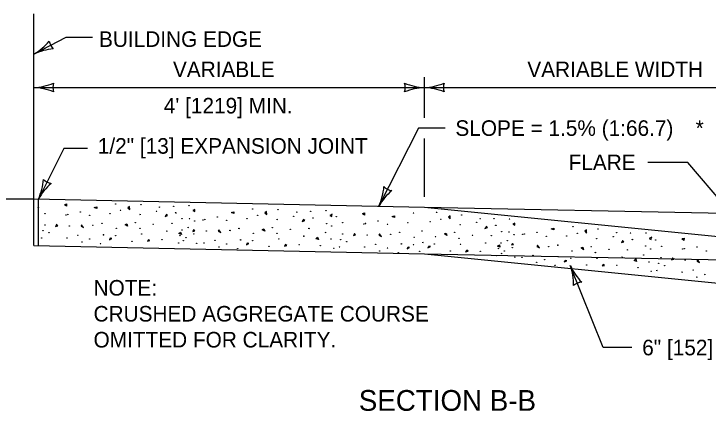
# Model space of a CAD drawing. Extents: x 49987.9 to 50021, y 49987.6 to 50011.4.
# Drawn here: x 50004.279 to 50006.956, y 50003.256 to 50004.787 of the extents above; entities that cross this region are included whole.
import ezdxf

# ---------------------------------------------------------------- set-up
doc = ezdxf.new("R2010")
doc.units = 0
for name, color, linetype in [('Level 1', 7, 'Continuous'), ('Level 2', 7, 'Continuous'), ('Level 3', 7, 'Continuous'), ('Level 4', 7, 'Continuous')]:
    doc.layers.add(name, color=color, linetype=linetype)

msp = doc.modelspace()

# ---------------------------------------------------------------- linework, layer by layer
at = {"layer": 'Level 1'}
for p, q in [((50004.3555, 50004.0737), (50004.3555, 50004.7866)), ((50003.4796, 50004.0736), (50004.3555, 50004.0737)), ((50004.3555, 50003.8937), (50004.3555, 50004.0737)), ((50004.3555, 50004.0737), (50005.8615, 50004.0421)), ((50004.3733, 50003.8933), (50004.3733, 50004.0733)), ((50004.5887, 50004.0402), (50004.5982, 50004.0433)), ((50004.5887, 50004.0402), (50004.5982, 50004.0433)), ((50004.5982, 50004.0371), (50004.5887, 50004.0402)), ((50004.5982, 50004.0371), (50004.5887, 50004.0402)), ((50004.5982, 50004.0433), (50004.5982, 50004.0371)), ((50004.5982, 50004.0433), (50004.5982, 50004.0371)), ((50004.9759, 50004.0334), (50004.9681, 50004.0288)), ((50004.9681, 50004.0288), (50004.9759, 50004.0249)), ((50004.9681, 50004.0288), (50004.9759, 50004.0249)), ((50004.9759, 50004.0249), (50004.9759, 50004.0334)), ((50004.9759, 50004.0249), (50004.9759, 50004.0326)), ((50005.1173, 50004.0209), (50005.1268, 50004.024)), ((50005.1173, 50004.0209), (50005.1268, 50004.024)), ((50005.1268, 50004.024), (50005.1268, 50004.0178)), ((50005.1268, 50004.024), (50005.1268, 50004.0178)), ((50005.8615, 50004.0421), (50007.3675, 50003.8919)), ((50005.8615, 50004.0421), (50007.3675, 50004.0119)), ((50005.1268, 50004.0178), (50005.1173, 50004.0209)), ((50005.1268, 50004.0178), (50005.1173, 50004.0209)), ((50005.7372, 50004.0055), (50005.7467, 50004.0086)), ((50005.7372, 50004.0055), (50005.7467, 50004.0086)), ((50005.7467, 50004.0024), (50005.7372, 50004.0055)), ((50005.7467, 50004.0024), (50005.7372, 50004.0055)), ((50005.7467, 50004.0086), (50005.7467, 50004.0024)), ((50005.7467, 50004.0086), (50005.7467, 50004.0024)), ((50004.7081, 50003.9744), (50004.7143, 50003.9774)), ((50004.7081, 50003.9744), (50004.7143, 50003.9774)), ((50004.7174, 50003.9681), (50004.7081, 50003.9744)), ((50004.7174, 50003.9681), (50004.7081, 50003.9744)), ((50004.7143, 50003.9774), (50004.7174, 50003.9681)), ((50004.7143, 50003.9774), (50004.7174, 50003.9681)), ((50006.211, 50003.9803), (50006.2029, 50003.9763)), ((50006.2029, 50003.9763), (50006.2104, 50003.9719)), ((50006.2029, 50003.9763), (50006.2104, 50003.9719)), ((50006.2104, 50003.9719), (50006.211, 50003.9803)), ((50006.2104, 50003.9719), (50006.2109, 50003.9796)), ((50004.915, 50003.9398), (50004.9214, 50003.946)), ((50004.915, 50003.9398), (50004.9214, 50003.946)), ((50004.9214, 50003.946), (50004.9245, 50003.9366)), ((50004.9214, 50003.946), (50004.9245, 50003.9366)), ((50004.9719, 50003.9546), (50004.9682, 50003.9486)), ((50004.9682, 50003.9486), (50004.9763, 50003.9506)), ((50004.9763, 50003.9506), (50004.9719, 50003.9546)), ((50005.2367, 50003.9551), (50005.2429, 50003.9581)), ((50005.2367, 50003.9551), (50005.2429, 50003.9581)), ((50005.246, 50003.9488), (50005.2367, 50003.9551)), ((50005.246, 50003.9488), (50005.2367, 50003.9551)), ((50005.2429, 50003.9581), (50005.246, 50003.9488)), ((50005.2429, 50003.9581), (50005.246, 50003.9488)), ((50006.3512, 50003.9584), (50006.3609, 50003.9609)), ((50006.3512, 50003.9584), (50006.3609, 50003.9609)), ((50006.3605, 50003.9547), (50006.3512, 50003.9584)), ((50006.3605, 50003.9547), (50006.3512, 50003.9584)), ((50006.3609, 50003.9609), (50006.3605, 50003.9547)), ((50006.3609, 50003.9609), (50006.3605, 50003.9547)), ((50004.7972, 50003.9165), (50004.7934, 50003.9109)), ((50004.8025, 50003.913), (50004.7972, 50003.9165)), ((50004.9245, 50003.9366), (50004.915, 50003.9398)), ((50004.9245, 50003.9366), (50004.915, 50003.9398)), ((50005.4436, 50003.9205), (50005.45, 50003.9267)), ((50005.4436, 50003.9205), (50005.45, 50003.9267)), ((50005.4531, 50003.9173), (50005.4436, 50003.9205)), ((50005.4531, 50003.9173), (50005.4436, 50003.9205)), ((50005.45, 50003.9267), (50005.4531, 50003.9173)), ((50005.45, 50003.9267), (50005.4531, 50003.9173)), ((50005.9398, 50003.9394), (50005.9462, 50003.942)), ((50005.9398, 50003.9394), (50005.9462, 50003.942)), ((50005.9487, 50003.9325), (50005.9398, 50003.9394)), ((50005.9487, 50003.9325), (50005.9398, 50003.9394)), ((50005.9462, 50003.942), (50005.9487, 50003.9325)), ((50005.9462, 50003.942), (50005.9487, 50003.9325)), ((50004.3555, 50003.8937), (50005.8615, 50003.8621)), ((50004.7934, 50003.9109), (50004.8025, 50003.913)), ((50006.144, 50003.891), (50006.1508, 50003.8968)), ((50006.144, 50003.891), (50006.1508, 50003.8968)), ((50006.1532, 50003.8872), (50006.144, 50003.891)), ((50006.1532, 50003.8872), (50006.144, 50003.891)), ((50006.1508, 50003.8968), (50006.1532, 50003.8872)), ((50006.1508, 50003.8968), (50006.1532, 50003.8872)), ((50006.2017, 50003.9021), (50006.1976, 50003.8963)), ((50006.1976, 50003.8963), (50006.2058, 50003.8977)), ((50006.2058, 50003.8977), (50006.2017, 50003.9021)), ((50005.8615, 50003.8621), (50007.3675, 50003.7119)), ((50006.0248, 50003.8757), (50006.0207, 50003.8703)), ((50006.0207, 50003.8703), (50006.0299, 50003.8718)), ((50006.0299, 50003.8718), (50006.0248, 50003.8757)), ((50006.466, 50003.8848), (50006.4723, 50003.8874)), ((50006.466, 50003.8848), (50006.4723, 50003.8874)), ((50006.4748, 50003.8779), (50006.466, 50003.8848)), ((50006.4748, 50003.8779), (50006.466, 50003.8848)), ((50006.4723, 50003.8874), (50006.4748, 50003.8779)), ((50006.4723, 50003.8874), (50006.4748, 50003.8779)), ((50006.6701, 50003.8365), (50006.6769, 50003.8422)), ((50006.6701, 50003.8365), (50006.6769, 50003.8422)), ((50006.6794, 50003.8326), (50006.6701, 50003.8365)), ((50006.6794, 50003.8326), (50006.6701, 50003.8365)), ((50006.6769, 50003.8422), (50006.6794, 50003.8326)), ((50006.6769, 50003.8422), (50006.6794, 50003.8326))]:
    msp.add_line(p, q, dxfattribs=at)
for points in [[(50004.4747, 50004.0524), (50004.4817, 50004.0542), (50004.4817, 50004.0454), (50004.474, 50004.0511)], [(50004.4747, 50004.0524), (50004.4817, 50004.0542), (50004.4817, 50004.0454), (50004.474, 50004.0511)], [(50004.7243, 50004.0448), (50004.718, 50004.0397), (50004.7255, 50004.0326), (50004.7243, 50004.0448)], [(50004.7243, 50004.0448), (50004.718, 50004.0397), (50004.7255, 50004.0326), (50004.7243, 50004.0448)], [(50005.2529, 50004.0255), (50005.2466, 50004.0204), (50005.2541, 50004.0133), (50005.2529, 50004.0255)], [(50005.2529, 50004.0255), (50005.2466, 50004.0204), (50005.2541, 50004.0133), (50005.2529, 50004.0255)], [(50004.8671, 50004.0133), (50004.8619, 50004.0057), (50004.8715, 50004.0095), (50004.8658, 50004.0141)], [(50004.8671, 50004.0133), (50004.8619, 50004.0057), (50004.8715, 50004.0095), (50004.8658, 50004.0141)], [(50005.5064, 50004.0152), (50005.4967, 50004.0095), (50005.5045, 50004.0056), (50005.5045, 50004.0133)], [(50005.5064, 50004.0152), (50005.4967, 50004.0095), (50005.5045, 50004.0056), (50005.5045, 50004.0133)], [(50005.6232, 50004.0177), (50005.6302, 50004.0195), (50005.6302, 50004.0107), (50005.6225, 50004.0164)], [(50005.6232, 50004.0177), (50005.6302, 50004.0195), (50005.6302, 50004.0107), (50005.6225, 50004.0164)], [(50005.9607, 50004.0085), (50005.9541, 50004.0039), (50005.9611, 50003.9963), (50005.9607, 50004.0085)], [(50005.9607, 50004.0085), (50005.9541, 50004.0039), (50005.9611, 50003.9963), (50005.9607, 50004.0085)], [(50004.4439, 50003.975), (50004.4396, 50003.9679), (50004.4477, 50003.9699), (50004.4421, 50003.975)], [(50004.4439, 50003.975), (50004.4396, 50003.9679), (50004.4477, 50003.9699), (50004.4421, 50003.975)], [(50004.54, 50003.9744), (50004.5375, 50003.9686), (50004.5477, 50003.9641), (50004.54, 50003.9744)], [(50004.54, 50003.9744), (50004.5375, 50003.9686), (50004.5477, 50003.9641), (50004.54, 50003.9744)], [(50005.3957, 50003.994), (50005.3905, 50003.9864), (50005.4001, 50003.9902), (50005.3944, 50003.9948)], [(50005.3957, 50003.994), (50005.3905, 50003.9864), (50005.4001, 50003.9902), (50005.3944, 50003.9948)], [(50005.0686, 50003.9551), (50005.0661, 50003.9493), (50005.0763, 50003.9448), (50005.0686, 50003.9551)], [(50005.0686, 50003.9551), (50005.0661, 50003.9493), (50005.0763, 50003.9448), (50005.0686, 50003.9551)], [(50006.1011, 50003.9676), (50006.0954, 50003.9603), (50006.1052, 50003.9635), (50006.0998, 50003.9685)], [(50006.1011, 50003.9676), (50006.0954, 50003.9603), (50006.1052, 50003.9635), (50006.0998, 50003.9685)], [(50006.4868, 50003.954), (50006.4802, 50003.9493), (50006.4872, 50003.9417), (50006.4868, 50003.954)], [(50006.4868, 50003.954), (50006.4802, 50003.9493), (50006.4872, 50003.9417), (50006.4868, 50003.954)], [(50004.6495, 50003.9219), (50004.6468, 50003.9161), (50004.6564, 50003.9212), (50004.6501, 50003.9225)], [(50004.6495, 50003.9219), (50004.6468, 50003.9161), (50004.6564, 50003.9212), (50004.6501, 50003.9225)], [(50005.5924, 50003.9403), (50005.5881, 50003.9332), (50005.5962, 50003.9352), (50005.5906, 50003.9403)], [(50005.5924, 50003.9403), (50005.5881, 50003.9332), (50005.5962, 50003.9352), (50005.5906, 50003.9403)], [(50005.6885, 50003.9397), (50005.686, 50003.9339), (50005.6962, 50003.9294), (50005.6885, 50003.9397)], [(50005.6885, 50003.9397), (50005.686, 50003.9339), (50005.6962, 50003.9294), (50005.6885, 50003.9397)], [(50006.7391, 50003.9268), (50006.729, 50003.9217), (50006.7365, 50003.9173), (50006.7371, 50003.925)], [(50006.7391, 50003.9268), (50006.729, 50003.9217), (50006.7365, 50003.9173), (50006.7371, 50003.925)], [(50006.8558, 50003.9214), (50006.8629, 50003.9228), (50006.8623, 50003.914), (50006.855, 50003.9202)], [(50006.8558, 50003.9214), (50006.8629, 50003.9228), (50006.8623, 50003.914), (50006.855, 50003.9202)], [(50005.1781, 50003.9026), (50005.1754, 50003.8968), (50005.185, 50003.9019), (50005.1787, 50003.9032)], [(50005.1781, 50003.9026), (50005.1754, 50003.8968), (50005.185, 50003.9019), (50005.1787, 50003.9032)], [(50005.3259, 50003.8975), (50005.322, 50003.8916), (50005.3311, 50003.8937), (50005.3253, 50003.8975)], [(50005.3259, 50003.8975), (50005.322, 50003.8916), (50005.3311, 50003.8937), (50005.3253, 50003.8975)], [(50005.8779, 50003.8909), (50005.8748, 50003.8853), (50005.8847, 50003.8898), (50005.8785, 50003.8915)], [(50005.8779, 50003.8909), (50005.8748, 50003.8853), (50005.8847, 50003.8898), (50005.8785, 50003.8915)], [(50006.2982, 50003.896), (50006.2954, 50003.8904), (50006.3052, 50003.8853), (50006.2982, 50003.896)], [(50006.2982, 50003.896), (50006.2954, 50003.8904), (50006.3052, 50003.8853), (50006.2982, 50003.896)], [(50006.6272, 50003.913), (50006.6215, 50003.9058), (50006.6313, 50003.9089), (50006.626, 50003.9139)], [(50006.6272, 50003.913), (50006.6215, 50003.9058), (50006.6313, 50003.9089), (50006.626, 50003.9139)], [(50005.798, 50003.8872), (50005.7953, 50003.8814), (50005.8049, 50003.8865), (50005.7986, 50003.8878)], [(50005.798, 50003.8872), (50005.7953, 50003.8814), (50005.8049, 50003.8865), (50005.7986, 50003.8878)], [(50006.404, 50003.8363), (50006.4009, 50003.8307), (50006.4108, 50003.8352), (50006.4046, 50003.8369)], [(50006.404, 50003.8363), (50006.4009, 50003.8307), (50006.4108, 50003.8352), (50006.4046, 50003.8369)], [(50006.8199, 50003.8463), (50006.8151, 50003.8395), (50006.8233, 50003.8409), (50006.8181, 50003.8464)], [(50006.8199, 50003.8463), (50006.8151, 50003.8395), (50006.8233, 50003.8409), (50006.8181, 50003.8464)], [(50006.9157, 50003.8393), (50006.9128, 50003.8336), (50006.9227, 50003.8285), (50006.9157, 50003.8393)], [(50006.9157, 50003.8393), (50006.9128, 50003.8336), (50006.9227, 50003.8285), (50006.9157, 50003.8393)], [(50006.5511, 50003.8214), (50006.5468, 50003.8158), (50006.556, 50003.8172), (50006.5505, 50003.8214)], [(50006.5511, 50003.8214), (50006.5468, 50003.8158), (50006.556, 50003.8172), (50006.5505, 50003.8214)]]:
    msp.add_lwpolyline(points, dxfattribs=at)
for centre in [(50004.6713, 50004.0544), (50004.6713, 50004.0544), (50004.7686, 50004.0513), (50004.7686, 50004.0513), (50004.3733, 50004.0397), (50004.3733, 50004.0397), (50004.5345, 50004.0231), (50004.5345, 50004.0231), (50004.6897, 50004.0293), (50004.6897, 50004.0293), (50004.8287, 50004.0261), (50004.8287, 50004.0261), (50004.8408, 50004.0419), (50004.8408, 50004.0419), (50004.8945, 50004.0449), (50004.8945, 50004.0449), (50004.954, 50004.0481), (50004.954, 50004.0481), (50005.1999, 50004.0351), (50005.1999, 50004.0351), (50005.2972, 50004.032), (50005.2972, 50004.032), (50005.3694, 50004.0226), (50005.3694, 50004.0226), (50005.4231, 50004.0256), (50005.4231, 50004.0256), (50005.4826, 50004.0288), (50005.4826, 50004.0288), (50005.9085, 50004.0217), (50005.9085, 50004.0217), (50004.3983, 50004.0168), (50004.3983, 50004.0168), (50004.4797, 50004.0121), (50004.4797, 50004.0121), (50004.4862, 50004.0136), (50004.4862, 50004.0136), (50004.5709, 50004.0105), (50004.5709, 50004.0105), (50004.6494, 50004.0168), (50004.6494, 50004.0168), (50004.7655, 50004.0136), (50004.7655, 50004.0136), (50004.9019, 50004.0204), (50004.9019, 50004.0204), (50004.9036, 50004.0199), (50004.9036, 50004.0199), (50004.9269, 50003.9975), (50004.9269, 50003.9975), (50004.9558, 50003.998), (50004.9558, 50003.998), (50005.0631, 50004.0038), (50005.0631, 50004.0038), (50005.178, 50003.9975), (50005.178, 50003.9975), (50005.2183, 50004.01), (50005.2183, 50004.01), (50005.3573, 50004.0068), (50005.3573, 50004.0068), (50005.4322, 50004.0006), (50005.4322, 50004.0006), (50005.5218, 50004.005), (50005.5218, 50004.005), (50005.8198, 50004.0197), (50005.8198, 50004.0197), (50005.9251, 50003.9954), (50005.9251, 50003.9954), (50006.0053, 50004.0121), (50006.0053, 50004.0121), (50006.0767, 50003.9978), (50006.0767, 50003.9978), (50006.1305, 50003.9973), (50006.1305, 50003.9973), (50006.19, 50003.9965), (50006.19, 50003.9965), (50004.3983, 50003.9728), (50004.3983, 50003.9728), (50004.4925, 50003.9697), (50004.4925, 50003.9697), (50004.583, 50003.9714), (50004.583, 50003.9714), (50004.618, 50003.9791), (50004.618, 50003.9791), (50004.7467, 50003.9822), (50004.7467, 50003.9822), (50004.8157, 50003.976), (50004.8157, 50003.976), (50004.8879, 50003.9791), (50004.8879, 50003.9791), (50004.9757, 50003.9885), (50004.9757, 50003.9885), (50005.0083, 50003.9928), (50005.0083, 50003.9928), (50005.0148, 50003.9943), (50005.0148, 50003.9943), (50005.0995, 50003.9912), (50005.0995, 50003.9912), (50005.2941, 50003.9943), (50005.2941, 50003.9943), (50005.4844, 50003.9787), (50005.4844, 50003.9787), (50005.5043, 50003.9692), (50005.5043, 50003.9692), (50005.5468, 50003.9821), (50005.5468, 50003.9821), (50005.6282, 50003.9774), (50005.6282, 50003.9774), (50005.6347, 50003.9789), (50005.6347, 50003.9789), (50005.683, 50003.9884), (50005.683, 50003.9884), (50005.7194, 50003.9758), (50005.7194, 50003.9758), (50005.7979, 50003.9821), (50005.7979, 50003.9821), (50005.884, 50003.9856), (50005.884, 50003.9856), (50005.9997, 50003.9747), (50005.9997, 50003.9747), (50006.0636, 50003.983), (50006.0636, 50003.983), (50006.1362, 50003.9724), (50006.1362, 50003.9724), (50006.1379, 50003.9717), (50006.1379, 50003.9717), (50004.3907, 50003.951), (50004.3907, 50003.951), (50004.414, 50003.9432), (50004.414, 50003.9432), (50004.6738, 50003.9604), (50004.6738, 50003.9604), (50004.7646, 50003.9604), (50004.7646, 50003.9604), (50004.8681, 50003.9495), (50004.8681, 50003.9495), (50004.9269, 50003.9535), (50004.9511, 50003.9635), (50004.9511, 50003.9635), (50005.0211, 50003.9504), (50005.0211, 50003.9504), (50005.1116, 50003.9521), (50005.1116, 50003.9521), (50005.1466, 50003.9598), (50005.1466, 50003.9598), (50005.2753, 50003.9629), (50005.2753, 50003.9629), (50005.3443, 50003.9567), (50005.3443, 50003.9567), (50005.4165, 50003.9598), (50005.4165, 50003.9598), (50005.4797, 50003.9442), (50005.4797, 50003.9442), (50005.7665, 50003.9444), (50005.7665, 50003.9444), (50005.852, 50003.9499), (50005.852, 50003.9499), (50005.9788, 50003.9446), (50005.9788, 50003.9446), (50006.1597, 50003.9478), (50006.1597, 50003.9478), (50006.1885, 50003.9464), (50006.1885, 50003.9464), (50006.2959, 50003.945), (50006.2959, 50003.945), (50006.4346, 50003.9671), (50006.4346, 50003.9671), (50006.5314, 50003.9575), (50006.5314, 50003.9575), (50006.6028, 50003.9433), (50006.6028, 50003.9433), (50006.6566, 50003.9427), (50006.6566, 50003.9427), (50006.7162, 50003.9419), (50006.7162, 50003.9419), (50004.3858, 50003.9226), (50004.3858, 50003.9226), (50004.4831, 50003.9226), (50004.4831, 50003.9226), (50004.5253, 50003.9338), (50004.5253, 50003.9338), (50004.5709, 50003.9195), (50004.5709, 50003.9195), (50004.6243, 50003.9352), (50004.6243, 50003.9352), (50004.6713, 50003.932), (50004.6713, 50003.932), (50004.7718, 50003.9383), (50004.7718, 50003.9383), (50004.8502, 50003.9163), (50004.8502, 50003.9163), (50004.9193, 50003.9317), (50004.9193, 50003.9317), (50004.9426, 50003.9239), (50004.9426, 50003.9239), (50004.9726, 50003.9383), (50004.9726, 50003.9383), (50005.1529, 50003.9159), (50005.1529, 50003.9159), (50005.2024, 50003.9411), (50005.2024, 50003.9411), (50005.2932, 50003.9411), (50005.2932, 50003.9411), (50005.3004, 50003.919), (50005.3004, 50003.919), (50005.3967, 50003.9302), (50005.3967, 50003.9302), (50005.5012, 50003.919), (50005.5012, 50003.919), (50005.5392, 50003.9163), (50005.5392, 50003.9163), (50005.5468, 50003.9381), (50005.5468, 50003.9381), (50005.641, 50003.935), (50005.641, 50003.935), (50005.7315, 50003.9367), (50005.7315, 50003.9367), (50005.8223, 50003.9257), (50005.8223, 50003.9257), (50005.9046, 50003.9277), (50005.9046, 50003.9277), (50005.9952, 50003.9217), (50005.9952, 50003.9217), (50006.0473, 50003.9338), (50006.0473, 50003.9338), (50006.1195, 50003.9321), (50006.1195, 50003.9321), (50006.2078, 50003.9356), (50006.2078, 50003.9356), (50006.2406, 50003.9377), (50006.2406, 50003.9377), (50006.2471, 50003.9388), (50006.2471, 50003.9388), (50006.3315, 50003.93), (50006.3315, 50003.93), (50006.4102, 50003.931), (50006.4102, 50003.931), (50006.4512, 50003.9408), (50006.4512, 50003.9408), (50006.5258, 50003.9201), (50006.5258, 50003.9201), (50006.5898, 50003.9284), (50006.5898, 50003.9284), (50006.664, 50003.9172), (50006.664, 50003.9172), (50006.7537, 50003.9156), (50006.7537, 50003.9156), (50004.5408, 50003.9072), (50004.5408, 50003.9072), (50004.6127, 50003.9009), (50004.6127, 50003.9009), (50004.7341, 50003.9101), (50004.7341, 50003.9101), (50004.9144, 50003.9033), (50004.9144, 50003.9033), (50004.9318, 50003.9132), (50004.9318, 50003.9132), (50004.9839, 50003.9025), (50004.9839, 50003.9025), (50005.0117, 50003.9033), (50005.0117, 50003.9033), (50005.0539, 50003.9145), (50005.0539, 50003.9145), (50005.0694, 50003.8879), (50005.0694, 50003.8879), (50005.0995, 50003.9002), (50005.0995, 50003.9002), (50005.1999, 50003.9127), (50005.1999, 50003.9127), (50005.2627, 50003.8908), (50005.2627, 50003.8908), (50005.3788, 50003.897), (50005.3788, 50003.897), (50005.4604, 50003.8939), (50005.4604, 50003.8939), (50005.5343, 50003.8879), (50005.5343, 50003.8879), (50005.5625, 50003.9085), (50005.5625, 50003.9085), (50005.6316, 50003.8879), (50005.6316, 50003.8879), (50005.6738, 50003.8991), (50005.6738, 50003.8991), (50005.7728, 50003.9005), (50005.7728, 50003.9005), (50005.8198, 50003.8973), (50005.8198, 50003.8973), (50005.8562, 50003.9057), (50005.8562, 50003.9057), (50005.9003, 50003.8996), (50005.9003, 50003.8996), (50006.0009, 50003.8991), (50006.0009, 50003.8991), (50006.0978, 50003.9038), (50006.0978, 50003.9038), (50006.1567, 50003.9039), (50006.1815, 50003.9123), (50006.1815, 50003.9123), (50006.3409, 50003.8902), (50006.3409, 50003.8902), (50006.3763, 50003.8955), (50006.3763, 50003.8955), (50006.5049, 50003.8901), (50006.5049, 50003.8901), (50006.7146, 50003.8918), (50006.7146, 50003.8918), (50006.7771, 50003.891), (50006.7771, 50003.891), (50006.9134, 50003.8883), (50006.9134, 50003.8883), (50005.1413, 50003.8816), (50005.1413, 50003.8816), (50005.5125, 50003.8832), (50005.5125, 50003.8832), (50005.6893, 50003.8725), (50005.6893, 50003.8725), (50005.7194, 50003.8848), (50005.7194, 50003.8848), (50005.7612, 50003.8662), (50005.7612, 50003.8662), (50005.8431, 50003.8721), (50005.8431, 50003.8721), (50005.9614, 50003.8735), (50005.9614, 50003.8735), (50006.0777, 50003.872), (50006.0777, 50003.872), (50006.1477, 50003.8827), (50006.1477, 50003.8827), (50006.1589, 50003.8634), (50006.1589, 50003.8634), (50006.1704, 50003.8733), (50006.1704, 50003.8733), (50006.2013, 50003.8857), (50006.2013, 50003.8857), (50006.4307, 50003.8732), (50006.4307, 50003.8732), (50006.5213, 50003.8671), (50006.5213, 50003.8671), (50006.5734, 50003.8792), (50006.5734, 50003.8792), (50006.6456, 50003.8775), (50006.6456, 50003.8775), (50006.7339, 50003.881), (50006.7339, 50003.881), (50006.858, 50003.8809), (50006.858, 50003.8809), (50006.8646, 50003.882), (50006.8646, 50003.882), (50006.9489, 50003.8732), (50006.9489, 50003.8732), (50006.1408, 50003.8547), (50006.1408, 50003.8547), (50006.2102, 50003.8492), (50006.2102, 50003.8492), (50006.2379, 50003.8482), (50006.2379, 50003.8482), (50006.2808, 50003.8565), (50006.2808, 50003.8565), (50006.3254, 50003.8392), (50006.3254, 50003.8392), (50006.3797, 50003.8513), (50006.3797, 50003.8513), (50006.4264, 50003.845), (50006.4264, 50003.845), (50006.527, 50003.8446), (50006.527, 50003.8446), (50006.6239, 50003.8493), (50006.6239, 50003.8493), (50006.7076, 50003.8578), (50006.7076, 50003.8578), (50006.7742, 50003.8472), (50006.7742, 50003.8472), (50006.8679, 50003.8377), (50006.8679, 50003.8377), (50006.2945, 50003.8289), (50006.2945, 50003.8289), (50006.3659, 50003.8179), (50006.3659, 50003.8179), (50006.4876, 50003.8189), (50006.4876, 50003.8189), (50006.6038, 50003.8174), (50006.6038, 50003.8174), (50006.685, 50003.8088), (50006.685, 50003.8088), (50006.7274, 50003.8311), (50006.7274, 50003.8311), (50006.7651, 50003.8259), (50006.7651, 50003.8259), (50006.7879, 50003.8166), (50006.7879, 50003.8166), (50006.7363, 50003.7946), (50006.7363, 50003.7946), (50006.7583, 50003.7979), (50006.7583, 50003.7979), (50006.8554, 50003.7914), (50006.8554, 50003.7914), (50006.8983, 50003.7998), (50006.8983, 50003.7998), (50006.9429, 50003.7824), (50006.9429, 50003.7824), (50006.9119, 50003.7722), (50006.9119, 50003.7722)]:
    msp.add_circle(centre, 0.000763, dxfattribs=at)
at = {"layer": 'Level 3'}
for p, q in [((50004.4789, 50004.6957), (50004.3555, 50004.6317)), ((50004.5814, 50004.6957), (50004.4789, 50004.6957)), ((50005.8615, 50004.3866), (50005.8615, 50004.5429)), ((50004.3555, 50004.5029), (50005.8615, 50004.5029)), ((50005.8615, 50004.5029), (50007.3675, 50004.5029)), ((50005.8387, 50004.3466), (50005.6864, 50004.0456)), ((50005.9412, 50004.3466), (50005.8387, 50004.3466)), ((50005.8615, 50004.0821), (50005.8615, 50004.3066)), ((50004.4718, 50004.2679), (50004.3733, 50004.0733)), ((50004.5623, 50004.2679), (50004.4718, 50004.2679)), ((50006.8778, 50004.2145), (50006.7235, 50004.2145)), ((50007.0699, 50003.9883), (50006.8778, 50004.2145)), ((50006.5508, 50003.501), (50006.4245, 50003.8171)), ((50006.6617, 50003.501), (50006.5508, 50003.501))]:
    msp.add_line(p, q, dxfattribs=at)
for centre, radius, start, end in [((50004.2381, 50004.833), 0.233, 300.2427, 319.4925), ((50004.4693, 50004.6907), 0.0548, 189.5542, 225.2765), ((50004.4496, 50004.4303), 0.2223, 94.8714, 115.0549), ((50004.344, 50004.7356), 0.233, 272.8273, 292.0772), ((50004.4837, 50004.5029), 0.0548, 162.1388, 197.8612), ((50005.8706, 50004.725), 0.2223, 247.456, 267.6395), ((50005.7332, 50004.5029), 0.0548, 342.1388, 17.8612), ((50005.85, 50004.7356), 0.233, 272.8273, 292.0772), ((50005.9897, 50004.5029), 0.0548, 162.1388, 197.8612), ((50004.3463, 50004.2807), 0.2223, 67.456, 87.6395), ((50005.8729, 50004.2701), 0.233, 92.8273, 112.0772), ((50005.8523, 50004.2807), 0.2223, 67.456, 87.6395), ((50004.1605, 50004.1681), 0.233, 335.9803, 355.2302), ((50004.5673, 50003.9648), 0.2223, 130.609, 150.7926), ((50004.4312, 50004.1877), 0.0548, 225.2919, 261.0142), ((50005.4735, 50004.1404), 0.233, 335.9803, 355.2302), ((50005.8804, 50003.9371), 0.2223, 130.609, 150.7926), ((50005.7443, 50004.16), 0.0548, 225.2919, 261.0142), ((50006.2148, 50003.7433), 0.2223, 359.2169, 19.4004), ((50006.6364, 50003.9141), 0.233, 204.5882, 223.8381), ((50006.4721, 50003.698), 0.0548, 93.8997, 129.6221)]:
    msp.add_arc(centre, radius, start, end, dxfattribs=at)
at = {"layer": 'Level 4'}
msp.add_line((50005.8615, 50003.8621), (50007.3675, 50003.832), dxfattribs=at)

# ---------------------------------------------------------------- texts
at = {"layer": 'Level 2'}
for s, height, p in [('BUILDING EDGE', 0.06, (50004.6069, 50004.6594)), ('VARIABLE', 0.06, (50004.8921, 50004.5429)), ('VARIABLE WIDTH', 0.06, (50006.2587, 50004.5429)), ("4' [1219] MIN.", 0.06, (50004.8567, 50004.4029)), ('SLOPE = 1.5% (1:66.7)', 0.06, (50005.9812, 50004.3166)), ('*', 0.06, (50006.9078, 50004.3166)), ('1/2" [13] EXPANSION JOINT', 0.06, (50004.6023, 50004.2479)), ('FLARE', 0.06, (50006.4178, 50004.1845)), ('NOTE:', 0.06, (50004.5858, 50003.7012)), ('CRUSHED AGGREGATE COURSE', 0.06, (50004.5858, 50003.6012)), ('OMITTED FOR CLARITY.', 0.06, (50004.5858, 50003.5012)), ('6" [152] SIDEWALK FOR APPROACH', 0.06, (50006.7017, 50003.471)), ('SECTION B-B', 0.08, (50005.6087, 50003.2572))]:
    msp.add_text(s, height=height, dxfattribs=at).set_placement(p)

doc.saveas('drawing.dxf')
